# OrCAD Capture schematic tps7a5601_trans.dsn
size A; title: TPS7A56 6A, Low-VIN Ultra-Low Dropout Voltage Regulator; rev: 1.0
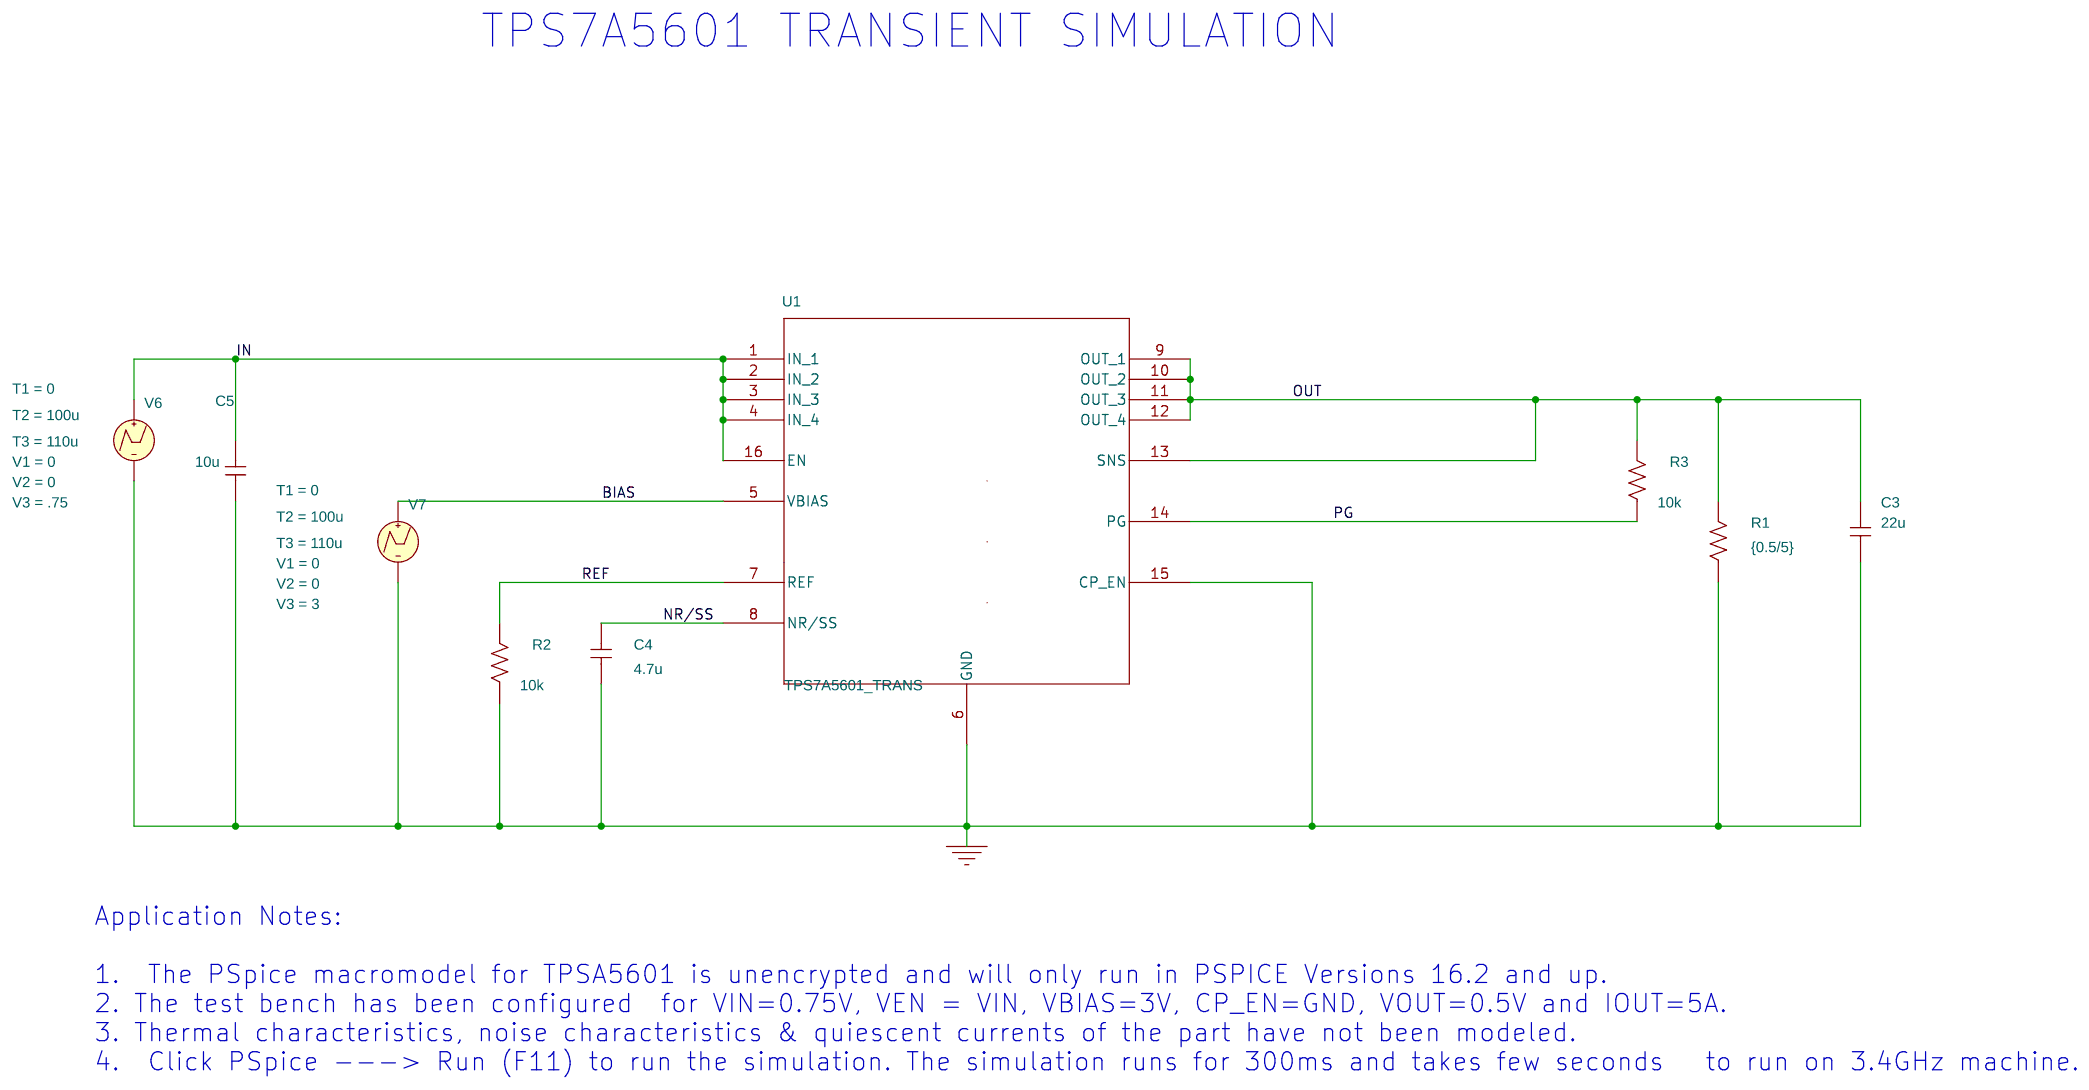
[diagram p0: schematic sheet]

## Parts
C3  22u  [RAD/CK05]
C4  4.7u  [RAD/CK05]
C5  10u  [RAD/CK05]
R1  {0.5/5}  [AX/RC05]
R2  10k  [AX/RC05]
R3  10k  [AX/RC05]
U1  TPS7A5601_TRANS  [RTE0016C]
V6  VPWL
V7  VPWL

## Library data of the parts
C3-C5 = C
R1-R3 = R
U1 = TPS7A5601_TRANS
V6 = VPWL: T1: 0; T2: 100u; T3: 110u; V1: 0; V2: 0; V3: .75
V7 = VPWL: T1: 0; T2: 100u; T3: 110u; V1: 0; V2: 0; V3: 3

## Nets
0: C3.1 C4.1 C5.1 R1.1 R2.1 U1.6(GND) U1.15(CP_EN) V6.2(-) V7.2(-)
BIAS: U1.5(VBIAS) V7.1(+)
IN: C5.2 U1.1(IN) U1.2(IN) U1.3(IN) U1.4(IN) U1.16(EN) V6.1(+)
NR/SS: C4.2 U1.8(NR/SS)
OUT: C3.2 R1.2 R3.2 U1.9(OUT_1) U1.10(OUT_2) U1.11(OUT_3) U1.12(OUT_4) U1.13(SNS)
PG: R3.1 U1.14(PG)
REF: R2.2 U1.7(REF)

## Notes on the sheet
- TPS7A5601 TRANSIENT SIMULATION
- Application Notes:
  1.  The PSpice macromodel for TPSA5601 is unencrypted and will only run in PSPICE Versions 16.2 and up.
  2. The test bench has been configured  for VIN=0.75V, VEN = VIN, VBIAS=3V, CP_EN=GND, VOUT=0.5V and IOUT=5A.
  3. Thermal characteristics, noise characteristics & quiescent currents of the part have not been modeled.
  4.  Click PSpice ---> Run (F11) to run the simulation. The simulation runs for 300ms and takes few seconds   to run on 3.4GHz machine.
